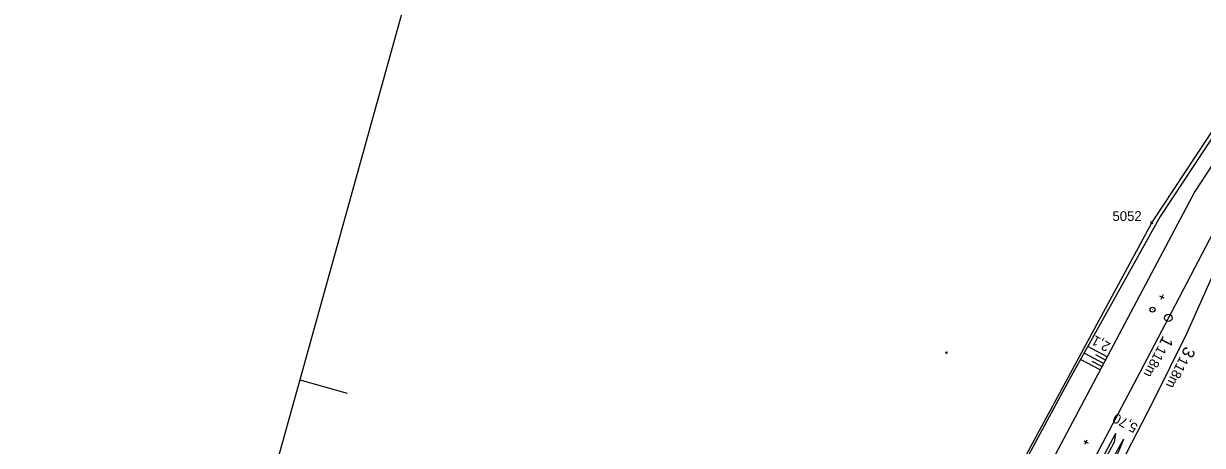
# Model space of a CAD drawing. Extents: x -795094 to -794639, y -1135368 to -1134681.
# Drawn here: x -795037.8 to -794797.7, y -1134896.9 to -1134811 of the extents above; entities that cross this region are included whole.
import ezdxf

# ---------------------------------------------------------------- set-up
doc = ezdxf.new("R2010")
doc.units = 0
for name, color, linetype in [('0381KM005-009P - Vrstva 1', 7, 'Continuous'), ('0381KM005-009P - Vrstva 48', 7, 'Continuous'), ('0381KM005-009P - Vrstva 49', 7, 'Continuous'), ('0381KM005-009P - Vrstva 7', 7, 'Continuous'), ('formát', 7, 'Continuous'), ('szdc - hran DP', 7, 'Continuous'), ('szdc - szdc_cislo', 7, 'Continuous'), ('szdc - szdc_krizek', 7, 'Continuous')]:
    doc.layers.add(name, color=color, linetype=linetype)

msp = doc.modelspace()

# ---------------------------------------------------------------- linework, layer by layer
at = {"layer": '0381KM005-009P - Vrstva 1'}
for points in [[(-794788.58, -1134840.28), (-794803.19, -1134868.16), (-794810.38, -1134881.86), (-794818.66, -1134897.6), (-794826.62, -1134912.5), (-794834.33, -1134926.85), (-794861.92, -1134977.99)], [(-794786.96, -1134841.36), (-794793.84, -1134858.32), (-794800.91, -1134874.12), (-794807.73, -1134887.87), (-794826.52, -1134924.29), (-794833.34, -1134937.13), (-794839.37, -1134947.86), (-794840.75, -1134950.16), (-794846.08, -1134958.61), (-794850.88, -1134965.55), (-794860.1, -1134978.74)]]:
    msp.add_lwpolyline(points, dxfattribs=at)
at = {"layer": '0381KM005-009P - Vrstva 48'}
for p, q in [((-794817.11, -1134878.83), (-794821.04, -1134876.75)), ((-794818.52, -1134881.48), (-794822.5, -1134879.37)), ((-794817.81, -1134880.16), (-794821.77, -1134878.06)), ((-794818.17, -1134880.82), (-794820.15, -1134879.77)), ((-794817.46, -1134879.49), (-794819.43, -1134878.45))]:
    msp.add_line(p, q, dxfattribs=at)
at = {"layer": '0381KM005-009P - Vrstva 49'}
for p, q in [((-794781.56, -1134812.71), (-794806.26, -1134850.22)), ((-794779.34, -1134814.68), (-794799.26, -1134845.15)), ((-794799.26, -1134845.15), (-794840.65, -1134923.24)), ((-794806.26, -1134850.22), (-794824.73, -1134883.39)), ((-794849.62, -1134877.9), (-794850.1, -1134878.05)), ((-794849.94, -1134877.74), (-794849.79, -1134878.21)), ((-794824.73, -1134883.39), (-794837.68, -1134907.33))]:
    msp.add_line(p, q, dxfattribs=at)
for points in [[(-794815.37, -1134894.44), (-794815.67, -1134896.21), (-794830.44, -1134923.9), (-794846.52, -1134953.51), (-794848.28, -1134955.61)], [(-794815.37, -1134894.44), (-794830.99, -1134923.68), (-794848.28, -1134955.61)], [(-794813.73, -1134895.61), (-794815.7, -1134900.49), (-794822, -1134912.52), (-794829.49, -1134927.01), (-794835.62, -1134938.73), (-794838.1, -1134942.66)], [(-794813.73, -1134895.61), (-794816.27, -1134900.06), (-794822.55, -1134912.27), (-794829.83, -1134926.6), (-794836.24, -1134938.45), (-794838.1, -1134942.66)]]:
    msp.add_lwpolyline(points, dxfattribs=at)
at = {"layer": '0381KM005-009P - Vrstva 7'}
for p, q in [((-794805.45, -1134866.91), (-794806.34, -1134866.45)), ((-794805.66, -1134866.24), (-794806.13, -1134867.13)), ((-794807.82, -1134869.17), (-794807.87, -1134869.26)), ((-794821.83, -1134895.92), (-794820.94, -1134896.39)), ((-794821.62, -1134896.6), (-794821.15, -1134895.71))]:
    msp.add_line(p, q, dxfattribs=at)
for centre, radius in [((-794807.84, -1134869.22), 0.5), ((-794804.63, -1134870.91), 0.75)]:
    msp.add_circle(centre, radius, dxfattribs=at)
at = {"layer": 'formát'}
for p, q in [((-794925.31, -1134681.22), (-794981.56, -1134883.54)), ((-794981.56, -1134883.54), (-795037.81, -1135085.87)), ((-794981.56, -1134883.54), (-794971.92, -1134886.22))]:
    msp.add_line(p, q, dxfattribs=at)
at = {"layer": 'szdc - hran DP'}
for p, q in [((-794808.02, -1134851.51), (-794775.44, -1134802.2)), ((-794834.03, -1134899.62), (-794808.02, -1134851.51))]:
    msp.add_line(p, q, dxfattribs=at)
at = {"layer": 'szdc - szdc_krizek'}
for p, q in [((-794807.76, -1134851.78), (-794808.29, -1134851.25)), ((-794808.29, -1134851.78), (-794807.76, -1134851.25))]:
    msp.add_line(p, q, dxfattribs=at)

# ---------------------------------------------------------------- texts
at = {"layer": '0381KM005-009P - Vrstva 1'}
for s, height, rotation, p in [('1', 2.5, 242.3222, (-794805.68, -1134874.39)), ('118m', 2, 242.2272, (-794806.66, -1134876.42)), ('3', 2.5, 243.6203, (-794801.22, -1134876.56)), ('118m', 2, 243.6203, (-794802.23, -1134878.61)), ('5,70', 2, 152.2272, (-794810.68, -1134892.67))]:
    msp.add_text(s, height=height, rotation=rotation, dxfattribs=at).set_placement(p)
at = {"layer": '0381KM005-009P - Vrstva 48'}
msp.add_text('2,1', height=2, rotation=152.0771, dxfattribs=at).set_placement((-794816.27, -1134876.14))
at = {"layer": 'szdc - szdc_cislo'}
msp.add_text('5052', height=2, dxfattribs=at).set_placement((-794816.01, -1134851.17))

doc.saveas('drawing.dxf')
